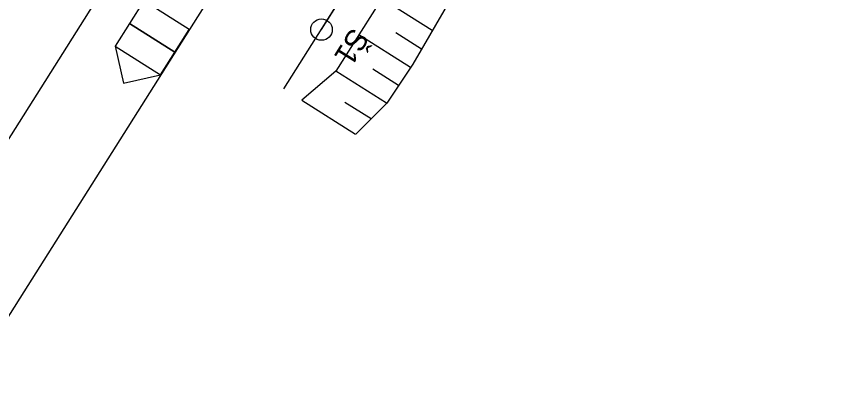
# Model space of a CAD drawing. Extents: x -743359 to -742769, y -1127804 to -1126284.
# Drawn here: x -743182.74 to -743163.64, y -1127113.5 to -1127104.78 of the extents above; entities that cross this region are included whole.
import ezdxf

# ---------------------------------------------------------------- set-up
doc = ezdxf.new("R2010")
doc.units = 0
for name, color, linetype in [('_Zabezpečovací zařízení', 7, 'Continuous'), ('_Zabezpečovací zařízení_trasa', 7, 'Continuous'), ('OSA', 7, 'Continuous'), ('SMER_VYS_VYROVNANI', 7, 'Continuous'), ('SVAH', 7, 'Continuous'), ('TRATIVOD', 7, 'Continuous')]:
    doc.layers.add(name, color=color, linetype=linetype)

msp = doc.modelspace()

# ---------------------------------------------------------------- linework, layer by layer
at = {"layer": '_Zabezpečovací zařízení'}
for p, q in [((-743179.773, -1127104.416), (-743180.44, -1127105.473)), ((-743178.716, -1127105.083), (-743179.773, -1127104.416)), ((-743179.05, -1127105.611), (-743180.107, -1127104.945)), ((-743179.383, -1127106.14), (-743178.716, -1127105.083)), ((-743180.44, -1127105.473), (-743179.383, -1127106.14)), ((-743180.44, -1127105.473), (-743180.245, -1127106.335)), ((-743180.245, -1127106.335), (-743179.383, -1127106.14))]:
    msp.add_line(p, q, dxfattribs=at)
msp.add_lwpolyline([(-743179.773, -1127104.416), (-743180.107, -1127104.945), (-743179.05, -1127105.611), (-743178.716, -1127105.083), (-743179.773, -1127104.416)], dxfattribs=at)
at = {"layer": '_Zabezpečovací zařízení_trasa'}
msp.add_lwpolyline([(-743098.647, -1126974.146), (-743125.94, -1127017.384), (-743152.604, -1127059.608), (-743175.023, -1127095.116), (-743199.163, -1127133.346), (-743215.971, -1127159.941), (-743232.818, -1127186.515), (-743247.456, -1127209.811), (-743254.52, -1127221.639), (-743261.299, -1127233.691), (-743264.155, -1127239.195), (-743264.862, -1127241.108), (-743267.337, -1127245.816), (-743268.289, -1127247.159), (-743271.711, -1127253.75), (-743281.122, -1127274.196), (-743291.923, -1127301.42), (-743296.724, -1127315.222), (-743301.116, -1127329.128), (-743306.787, -1127349.506), (-743311.536, -1127370.056), (-743315.693, -1127392.87), (-743318.79, -1127415.837)], dxfattribs=at)
at = {"layer": 'OSA'}
msp.add_lwpolyline([(-743169.53, -1127090.542), (-743178.712, -1127105.086)], dxfattribs=at)
at = {"layer": 'SMER_VYS_VYROVNANI'}
msp.add_lwpolyline([(-743178.712, -1127105.086), (-743197.526, -1127134.888)], dxfattribs=at)
at = {"layer": 'SVAH'}
for p, q in [((-743173.059, -1127105.107), (-743174.235, -1127104.364)), ((-743173.565, -1127105.97), (-743174.769, -1127105.21)), ((-743173.309, -1127105.54), (-743173.906, -1127105.163)), ((-743173.842, -1127106.386), (-743174.439, -1127106.009)), ((-743174.12, -1127106.803), (-743175.303, -1127106.055)), ((-743174.842, -1127107.529), (-743176.097, -1127106.736)), ((-743174.477, -1127107.163), (-743175.091, -1127106.782))]:
    msp.add_line(p, q, dxfattribs=at)
for points in [[(-743173.338, -1127101.419), (-743176.524, -1127106.467)], [(-743172.435, -1127101.512), (-743175.303, -1127106.055), (-743176.091, -1127106.731)], [(-743172.596, -1127104.307), (-743173.512, -1127105.891), (-743174.119, -1127106.803), (-743174.835, -1127107.522)]]:
    msp.add_lwpolyline(points, dxfattribs=at)
at = {"layer": 'TRATIVOD'}
msp.add_lwpolyline([(-743175.637, -1127105.086), (-743168.399, -1127093.621), (-743157.384, -1127076.172), (-743151.775, -1127072.311)], dxfattribs=at)
msp.add_circle((-743175.637, -1127105.086), 0.25, dxfattribs=at)

# ---------------------------------------------------------------- texts
msp.add_text('Š1', height=0.5, rotation=238, dxfattribs=at).set_placement((-743174.927, -1127105.012))

doc.saveas('drawing.dxf')
